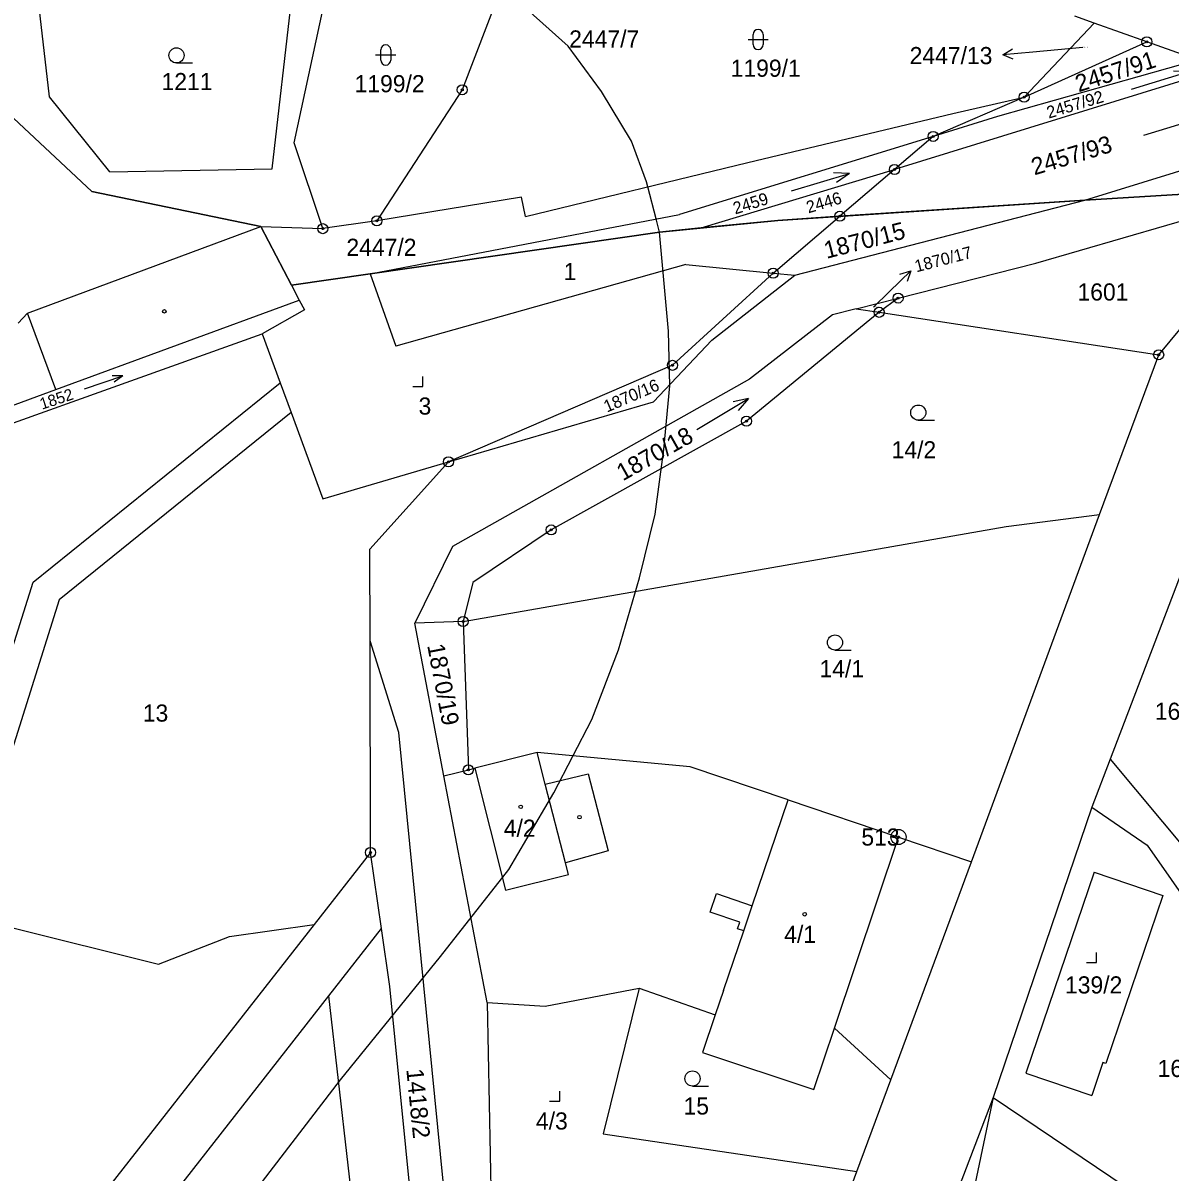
# Model space of a CAD drawing. Extents: x -546762 to -540209, y -1046851 to -1035694.
# Drawn here: x -543559.7 to -543445.9, y -1040689.9 to -1040575.9 of the extents above; entities that cross this region are included whole.
import ezdxf

# ---------------------------------------------------------------- set-up
doc = ezdxf.new("R2010")
doc.units = 0
for name, color, linetype in [('Vrstva 1', 7, 'Continuous'), ('Vrstva 13', 7, 'Continuous'), ('Vrstva 16', 7, 'Continuous'), ('Vrstva 17', 7, 'Continuous'), ('Vrstva 18', 7, 'Continuous'), ('Vrstva 19', 7, 'Continuous'), ('Vrstva 24', 7, 'Continuous'), ('Vrstva 25', 7, 'Continuous'), ('Vrstva 3', 7, 'Continuous'), ('Vrstva 30', 7, 'Continuous'), ('Vrstva 37', 7, 'Continuous'), ('Vrstva 4', 7, 'Continuous'), ('Vrstva 52', 7, 'Continuous')]:
    doc.layers.add(name, color=color, linetype=linetype)

msp = doc.modelspace()

# ---------------------------------------------------------------- linework, layer by layer
at = {"layer": 'Vrstva 1'}
for p, q in [((-543535.01, -1040590.37), (-543532.56, -1040569.26)), ((-543453.42, -1040575.92), (-543460.37, -1040583.26)), ((-543460.37, -1040583.26), (-543448.19, -1040577.78)), ((-543440.75, -1040580.42), (-543473.23, -1040590.44)), ((-543443.15, -1040579.57), (-543463, -1040585.19)), ((-543460.37, -1040583.26), (-543469.39, -1040587.16)), ((-543463, -1040585.19), (-543469.39, -1040587.16)), ((-543469.39, -1040587.16), (-543494.56, -1040594.9)), ((-543469.39, -1040587.16), (-543473.23, -1040590.44)), ((-543492.41, -1040596.24), (-543473.23, -1040590.44)), ((-543473.23, -1040590.44), (-543478.66, -1040595.08)), ((-543485.27, -1040600.73), (-543478.66, -1040595.08)), ((-543472.88, -1040603.2), (-543459.21, -1040599.73)), ((-543485.27, -1040600.73), (-543495.26, -1040609.87)), ((-543493.93, -1040599.87), (-543485.27, -1040600.73)), ((-543485.27, -1040600.73), (-543483.13, -1040600.94)), ((-543477.05, -1040604.26), (-543472.88, -1040603.2)), ((-543472.88, -1040603.2), (-543474.75, -1040604.61)), ((-543477.05, -1040604.26), (-543474.75, -1040604.61)), ((-543474.75, -1040604.61), (-543487.93, -1040615.41)), ((-543474.75, -1040604.61), (-543447.01, -1040608.82)), ((-543495.26, -1040609.87), (-543517.5, -1040619.45)), ((-543487.93, -1040615.41), (-543507.31, -1040626.2)), ((-543507.31, -1040626.2), (-543515.1, -1040631.43)), ((-543515.1, -1040631.43), (-543516.05, -1040635.29)), ((-543516.05, -1040635.29), (-543515.53, -1040650)), ((-543517.96, -1040650.61), (-543515.53, -1040650)), ((-543515.53, -1040650), (-543514.88, -1040649.84)), ((-543463.43, -1040682.52), (-543471.31, -1040703.06))]:
    msp.add_line(p, q, dxfattribs=at)
for points in [[(-543532.82, -1040587.78), (-543529.54, -1040572.59)], [(-543512.36, -1040572.67), (-543516.13, -1040582.53)], [(-543557.11, -1040583.24), (-543558.13, -1040574.33)], [(-543453.42, -1040575.92), (-543455.32, -1040575.24)], [(-543448.19, -1040577.78), (-543453.42, -1040575.92)], [(-543443.15, -1040579.57), (-543448.19, -1040577.78)], [(-543516.13, -1040582.53), (-543524.6, -1040595.53)], [(-543551.1, -1040590.66), (-543557.11, -1040583.24)], [(-543467.43, -1040584.9), (-543460.37, -1040583.26)], [(-543487.78, -1040589.76), (-543467.43, -1040584.9)], [(-543529.98, -1040596.31), (-543532.82, -1040587.78)], [(-543454.33, -1040593.48), (-543439.65, -1040588.95)], [(-543551.1, -1040590.66), (-543535.01, -1040590.37)], [(-543509.85, -1040595.1), (-543487.78, -1040589.76)], [(-543459.21, -1040599.73), (-543433.19, -1040592.18)], [(-543447.01, -1040608.82), (-543433.19, -1040592.18)], [(-543510.24, -1040593.2), (-543524.6, -1040595.53)], [(-543509.85, -1040595.1), (-543510.24, -1040593.2)], [(-543483.13, -1040600.94), (-543454.33, -1040593.48)], [(-543525.27, -1040600.79), (-543494.56, -1040594.9)], [(-543536.12, -1040596.1), (-543529.98, -1040596.31)], [(-543524.6, -1040595.53), (-543529.98, -1040596.31)], [(-543525.27, -1040600.79), (-543522.72, -1040607.98)], [(-543493.93, -1040599.87), (-543522.72, -1040607.98)], [(-543491.35, -1040607.37), (-543483.13, -1040600.94)], [(-543533.08, -1040601.92), (-543532.31, -1040603.39)], [(-543556.48, -1040612.28), (-543532.31, -1040603.39)], [(-543531.8, -1040604.36), (-543536, -1040606.75)], [(-543532.31, -1040603.39), (-543531.8, -1040604.36)], [(-543477.05, -1040604.26), (-543479.37, -1040604.85)], [(-543560.2, -1040605.68), (-543559.29, -1040604.69)], [(-543556.48, -1040612.28), (-543559.29, -1040604.69)], [(-543479.37, -1040604.85), (-543487.63, -1040611.24)], [(-543575.95, -1040621.03), (-543536, -1040606.75)], [(-543536, -1040606.75), (-543534.21, -1040611.62)], [(-543497.16, -1040613.5), (-543491.35, -1040607.37)], [(-543452.87, -1040624.67), (-543447.01, -1040608.82)], [(-543487.63, -1040611.24), (-543517.11, -1040627.83)], [(-543576.41, -1040619.61), (-543556.48, -1040612.28)], [(-543534.21, -1040611.62), (-543533.13, -1040614.55)], [(-543517.5, -1040619.45), (-543497.16, -1040613.5)], [(-543533.13, -1040614.55), (-543529.97, -1040623.1)], [(-543529.97, -1040623.1), (-543517.5, -1040619.45)], [(-543525.29, -1040628.11), (-543517.5, -1040619.45)], [(-543465.6, -1040659.12), (-543452.87, -1040624.67)], [(-543462.15, -1040625.86), (-543452.87, -1040624.67)], [(-543516.05, -1040635.29), (-543462.15, -1040625.86)], [(-543525.27, -1040637.19), (-543525.29, -1040628.11)], [(-543517.11, -1040627.83), (-543520.85, -1040635.46)], [(-543444.61, -1040630.05), (-543451.84, -1040648.94)], [(-543516.05, -1040635.29), (-543520.85, -1040635.46)], [(-543517.96, -1040650.61), (-543520.85, -1040635.46)], [(-543525.24, -1040658.21), (-543525.27, -1040637.19)], [(-543522.42, -1040646.29), (-543525.27, -1040637.19)], [(-543516.63, -1040704.88), (-543522.42, -1040646.29)], [(-543508.71, -1040648.29), (-543514.88, -1040649.84)], [(-543493.51, -1040649.69), (-543508.71, -1040648.29)], [(-543483.8, -1040652.97), (-543493.51, -1040649.69)], [(-543451.84, -1040648.94), (-543453.66, -1040653.7)], [(-543451.84, -1040648.94), (-543444.11, -1040658.18)], [(-543513.66, -1040673.1), (-543517.96, -1040650.61)], [(-543487.35, -1040663.48), (-543483.8, -1040652.97)], [(-543483.8, -1040652.97), (-543472.82, -1040656.68)], [(-543453.66, -1040653.7), (-543463.43, -1040682.52)], [(-543453.66, -1040653.7), (-543448.16, -1040657.49)], [(-543472.82, -1040656.68), (-543465.6, -1040659.12)], [(-543448.16, -1040657.49), (-543441, -1040667.68)], [(-543525.24, -1040658.21), (-543530.83, -1040665.34)], [(-543524.15, -1040665.74), (-543525.24, -1040658.21)], [(-543473.61, -1040680.77), (-543465.6, -1040659.12)], [(-543453.42, -1040660.16), (-543460.18, -1040680.1)], [(-543453.42, -1040660.16), (-543446.6, -1040662.48)], [(-543491.53, -1040664.13), (-543490.9, -1040662.28)], [(-543490.9, -1040662.28), (-543487.35, -1040663.48)], [(-543446.6, -1040662.48), (-543452.25, -1040679.14)], [(-543488.59, -1040665.12), (-543491.53, -1040664.13)], [(-543530.83, -1040665.34), (-543604.69, -1040759.58)], [(-543561.02, -1040665.62), (-543546.28, -1040669.29)], [(-543539.24, -1040666.55), (-543530.83, -1040665.34)], [(-543529.38, -1040672.42), (-543524.15, -1040665.74)], [(-543523.32, -1040671.49), (-543524.15, -1040665.74)], [(-543488.81, -1040665.78), (-543488.59, -1040665.12)], [(-543488.2, -1040665.99), (-543488.81, -1040665.78)], [(-543546.28, -1040669.29), (-543539.24, -1040666.55)], [(-543490.2, -1040671.91), (-543488.2, -1040665.99)], [(-543519.05, -1040714.41), (-543523.32, -1040671.49)], [(-543507.92, -1040673.46), (-543498.56, -1040671.65)], [(-543498.56, -1040671.65), (-543502.16, -1040686.11)], [(-543498.56, -1040671.65), (-543491.03, -1040674.32)], [(-543569.83, -1040724.11), (-543529.38, -1040672.42)], [(-543526.51, -1040697.64), (-543529.38, -1040672.42)], [(-543490.2, -1040671.91), (-543491.03, -1040674.32)], [(-543513.66, -1040673.1), (-543507.92, -1040673.46)], [(-543513.66, -1040673.1), (-543513.27, -1040693.2)], [(-543491.03, -1040674.32), (-543492.3, -1040678.04)], [(-543481.24, -1040681.72), (-543479.19, -1040675.62)], [(-543479.19, -1040675.62), (-543473.61, -1040680.77)], [(-543492.3, -1040678.04), (-543481.24, -1040681.72)], [(-543452.54, -1040679.05), (-543453.65, -1040682.31)], [(-543452.25, -1040679.14), (-543452.54, -1040679.05)], [(-543476.97, -1040689.86), (-543473.61, -1040680.77)], [(-543460.18, -1040680.1), (-543453.65, -1040682.31)], [(-543463.43, -1040682.52), (-543466.89, -1040698.87)], [(-543463.43, -1040682.52), (-543442.94, -1040696.32)], [(-543502.16, -1040686.11), (-543476.97, -1040689.86)], [(-543478.72, -1040694.6), (-543476.97, -1040689.86)]]:
    msp.add_lwpolyline(points, dxfattribs=at)
at = {"layer": 'Vrstva 13'}
for p, q in [((-543478.66, -1040595.08), (-543454.33, -1040593.48)), ((-543478.66, -1040595.08), (-543454.33, -1040593.48)), ((-543484.82, -1040595.49), (-543478.66, -1040595.08)), ((-543484.82, -1040595.49), (-543478.66, -1040595.08))]:
    msp.add_line(p, q, dxfattribs=at)
for points in [[(-543561.17, -1040584.9), (-543552.9, -1040592.63)], [(-543561.17, -1040584.9), (-543552.9, -1040592.63)], [(-543552.9, -1040592.63), (-543536.12, -1040596.1)], [(-543552.9, -1040592.63), (-543536.12, -1040596.1)], [(-543454.33, -1040593.48), (-543433.19, -1040592.18)], [(-543454.33, -1040593.48), (-543433.19, -1040592.18)], [(-543536.12, -1040596.1), (-543533.08, -1040601.92)], [(-543536.12, -1040596.1), (-543533.08, -1040601.92)], [(-543496.57, -1040596.65), (-543492.41, -1040596.24)], [(-543496.57, -1040596.65), (-543492.41, -1040596.24)], [(-543492.41, -1040596.24), (-543484.82, -1040595.49)], [(-543492.41, -1040596.24), (-543484.82, -1040595.49)], [(-543525.27, -1040600.79), (-543496.57, -1040596.65)], [(-543525.27, -1040600.79), (-543496.57, -1040596.65)], [(-543533.08, -1040601.92), (-543525.27, -1040600.79)], [(-543533.08, -1040601.92), (-543525.27, -1040600.79)]]:
    msp.add_lwpolyline(points, dxfattribs=at)
at = {"layer": 'Vrstva 16'}
for p, q in [((-543459.49, -1040578.8), (-543462.48, -1040579.07)), ((-543473.77, -1040602.58), (-543471.62, -1040600.49))]:
    msp.add_line(p, q, dxfattribs=at)
for points in [[(-543461.44, -1040579.48), (-543462.48, -1040579.07), (-543461.53, -1040578.48)], [(-543454.55, -1040578.35), (-543459.49, -1040578.8)], [(-543472.69, -1040600.83), (-543471.62, -1040600.49), (-543471.99, -1040601.54)], [(-543475.33, -1040604.1), (-543473.77, -1040602.58)]]:
    msp.add_lwpolyline(points, dxfattribs=at)
at = {"layer": 'Vrstva 24'}
for centre, radius in [((-543448.19, -1040577.78), 0.5), ((-543448.19, -1040577.78), 0.1), ((-543516.13, -1040582.53), 0.5), ((-543516.13, -1040582.53), 0.1), ((-543460.37, -1040583.26), 0.5), ((-543460.37, -1040583.26), 0.1), ((-543469.39, -1040587.16), 0.5), ((-543469.39, -1040587.16), 0.1), ((-543473.23, -1040590.44), 0.5), ((-543473.23, -1040590.44), 0.1), ((-543524.6, -1040595.53), 0.5), ((-543478.66, -1040595.08), 0.5), ((-543478.66, -1040595.08), 0.1), ((-543529.98, -1040596.31), 0.5), ((-543529.98, -1040596.31), 0.1), ((-543524.6, -1040595.53), 0.1), ((-543485.27, -1040600.73), 0.5), ((-543485.27, -1040600.73), 0.1), ((-543472.88, -1040603.2), 0.5), ((-543472.88, -1040603.2), 0.1), ((-543474.75, -1040604.61), 0.5), ((-543474.75, -1040604.61), 0.1), ((-543447.01, -1040608.82), 0.5), ((-543447.01, -1040608.82), 0.1), ((-543495.26, -1040609.87), 0.5), ((-543495.26, -1040609.87), 0.1), ((-543487.93, -1040615.41), 0.5), ((-543487.93, -1040615.41), 0.1), ((-543517.5, -1040619.45), 0.5), ((-543517.5, -1040619.45), 0.1), ((-543507.31, -1040626.2), 0.5), ((-543507.31, -1040626.2), 0.1), ((-543516.05, -1040635.29), 0.5), ((-543516.05, -1040635.29), 0.1), ((-543515.53, -1040650), 0.5), ((-543515.53, -1040650), 0.1), ((-543472.83, -1040656.67), 0.75), ((-543472.83, -1040656.67), 0.1), ((-543525.24, -1040658.21), 0.5), ((-543525.24, -1040658.21), 0.1)]:
    msp.add_circle(centre, radius, dxfattribs=at)
at = {"layer": 'Vrstva 25'}
for p, q in [((-543487.27, -1040578.04), (-543487.27, -1040577.04)), ((-543486.27, -1040577.04), (-543486.27, -1040578.04)), ((-543487.77, -1040577.54), (-543485.77, -1040577.54)), ((-543524.73, -1040579.08), (-543522.73, -1040579.08)), ((-543524.23, -1040579.58), (-543524.23, -1040578.58)), ((-543523.23, -1040578.58), (-543523.23, -1040579.58)), ((-543544.5, -1040579.87), (-543542.9, -1040579.87)), ((-543470.87, -1040615.31), (-543469.27, -1040615.31)), ((-543479.14, -1040638.12), (-543477.54, -1040638.12)), ((-543493.28, -1040681.38), (-543491.68, -1040681.38))]:
    msp.add_line(p, q, dxfattribs=at)
for points in [[(-543449.71, -1040582.47), (-543443.97, -1040580.73), (-543445.55, -1040580.69)], [(-543448.48, -1040587.02), (-543442.74, -1040585.28), (-543444.32, -1040585.24)], [(-543483.45, -1040592.55), (-543477.71, -1040590.83), (-543479.29, -1040590.78)], [(-543477.71, -1040590.83), (-543479, -1040591.74)], [(-543553.63, -1040612.19), (-543549.83, -1040610.91), (-543550.89, -1040610.91)], [(-543549.83, -1040610.91), (-543550.67, -1040611.55)], [(-543521.04, -1040611.97), (-543520.04, -1040611.97), (-543520.04, -1040610.97)], [(-543492.85, -1040616.24), (-543487.71, -1040613.16), (-543489.25, -1040613.5)], [(-543487.71, -1040613.16), (-543488.74, -1040614.36)], [(-543454.19, -1040669.13), (-543453.19, -1040669.13), (-543453.19, -1040668.13)], [(-543507.46, -1040682.88), (-543506.46, -1040682.88), (-543506.46, -1040681.88)]]:
    msp.add_lwpolyline(points, dxfattribs=at)
for centre, radius in [((-543544.5, -1040579.12), 0.75), ((-543545.7, -1040604.52), 0.175), ((-543470.87, -1040614.56), 0.75), ((-543479.14, -1040637.37), 0.75), ((-543510.33, -1040653.68), 0.175), ((-543504.5, -1040654.7), 0.175), ((-543482.14, -1040664.33), 0.175), ((-543493.28, -1040680.63), 0.75)]:
    msp.add_circle(centre, radius, dxfattribs=at)
for centre, start, end in [((-543486.77, -1040577.04), 0, 180), ((-543523.73, -1040578.58), 0, 180), ((-543486.77, -1040578.04), 180, 0), ((-543523.73, -1040579.58), 180, 0)]:
    msp.add_arc(centre, 0.5, start, end, dxfattribs=at)
at = {"layer": 'Vrstva 3'}
for points in [[(-543508.71, -1040648.29), (-543514.88, -1040649.84)], [(-543507.9, -1040651.42), (-543508.71, -1040648.29)], [(-543514.88, -1040649.84), (-543511.83, -1040661.93)], [(-543505.89, -1040659.22), (-543507.9, -1040651.42)], [(-543487.35, -1040663.48), (-543483.8, -1040652.97)], [(-543483.8, -1040652.97), (-543472.82, -1040656.68)], [(-543479.19, -1040675.62), (-543472.82, -1040656.68)], [(-543505.58, -1040660.4), (-543505.89, -1040659.22)], [(-543511.83, -1040661.93), (-543505.58, -1040660.4)], [(-543488.2, -1040665.99), (-543487.35, -1040663.48)], [(-543490.2, -1040671.91), (-543488.2, -1040665.99)], [(-543490.2, -1040671.91), (-543491.03, -1040674.32)], [(-543491.03, -1040674.32), (-543492.3, -1040678.04)], [(-543481.24, -1040681.72), (-543479.19, -1040675.62)], [(-543492.3, -1040678.04), (-543481.24, -1040681.72)]]:
    msp.add_lwpolyline(points, dxfattribs=at)
at = {"layer": 'Vrstva 30'}
for points in [[(-543558.73, -1040631.38), (-543534.21, -1040611.62)], [(-543534.21, -1040611.62), (-543533.13, -1040614.55)], [(-543533.13, -1040614.55), (-543556.14, -1040633.14)], [(-543568.97, -1040663.86), (-543558.73, -1040631.38)], [(-543556.14, -1040633.14), (-543566.03, -1040664.51)]]:
    msp.add_lwpolyline(points, dxfattribs=at)
at = {"layer": 'Vrstva 37'}
for centre in [(-543510.33, -1040653.68), (-543482.14, -1040664.33)]:
    msp.add_circle(centre, 0.175, dxfattribs=at)
at = {"layer": 'Vrstva 4'}
for points in [[(-543559.29, -1040604.69), (-543536.12, -1040596.1)], [(-543507.9, -1040651.42), (-543508.71, -1040648.29)], [(-543514.88, -1040649.84), (-543511.83, -1040661.93)], [(-543507.9, -1040651.42), (-543503.62, -1040650.39)], [(-543503.62, -1040650.39), (-543501.65, -1040658.05)], [(-543505.89, -1040659.22), (-543507.9, -1040651.42)], [(-543479.19, -1040675.62), (-543472.82, -1040656.68)], [(-543501.65, -1040658.05), (-543505.89, -1040659.22)], [(-543505.58, -1040660.4), (-543505.89, -1040659.22)], [(-543511.83, -1040661.93), (-543505.58, -1040660.4)], [(-543488.2, -1040665.99), (-543487.35, -1040663.48)]]:
    msp.add_lwpolyline(points, dxfattribs=at)
at = {"layer": 'Vrstva 52'}
for points in [[(-543496.57, -1040596.65), (-543525.27, -1040600.79), (-543533.08, -1040601.92), (-543536.12, -1040596.1), (-543552.9, -1040592.63), (-543561.17, -1040584.9), (-543563.03, -1040579.77), (-543571.38, -1040556.86)], [(-543496.57, -1040596.65), (-543496.9, -1040595.35), (-543497.71, -1040592.16), (-543497.84, -1040591.67), (-543499.33, -1040587.63), (-543502.32, -1040582.7), (-543505.61, -1040578.22), (-543511.58, -1040572.84), (-543511.85, -1040572.67), (-543512.26, -1040572.42), (-543513.49, -1040571.66), (-543517.41, -1040569.25), (-543523.53, -1040566.26)], [(-543563.03, -1040579.77), (-543561.17, -1040584.9), (-543552.9, -1040592.63), (-543536.12, -1040596.1), (-543533.08, -1040601.92), (-543525.27, -1040600.79), (-543496.57, -1040596.65)], [(-543496.57, -1040596.65), (-543484.82, -1040595.49), (-543454.33, -1040593.48), (-543433.19, -1040592.18), (-543425.03, -1040591.54), (-543423.93, -1040592.18)], [(-543413.87, -1040598.02), (-543423.93, -1040592.18), (-543425.03, -1040591.54), (-543433.19, -1040592.18), (-543454.33, -1040593.48), (-543478.66, -1040595.08), (-543484.82, -1040595.49), (-543492.41, -1040596.24), (-543496.57, -1040596.65)], [(-543761.66, -1041076.07), (-543723.84, -1040985.67), (-543700.74, -1040927.15), (-543689.29, -1040898.52), (-543681.03, -1040882.19), (-543673.88, -1040867.03), (-543658.41, -1040843.09), (-543543.36, -1040700.5), (-543528.22, -1040680.75), (-543518.29, -1040668.51), (-543511.51, -1040659.9), (-543507.03, -1040652.27), (-543503.28, -1040645), (-543500.61, -1040638.09), (-543498.55, -1040630.94), (-543496.98, -1040624.64), (-543496.13, -1040618.22), (-543495.53, -1040611.92), (-543495.65, -1040606.47), (-543496.57, -1040596.65)]]:
    msp.add_lwpolyline(points, dxfattribs=at)

# ---------------------------------------------------------------- texts
at = {"layer": 'Vrstva 16'}
for s, p in [('2447/7', (-543505.52, -1040578.34)), ('2447/13', (-543471.73, -1040579.99))]:
    msp.add_text(s, height=1.7, dxfattribs=at).set_placement(p)
msp.add_text('1870/17', height=1.2, rotation=14.522, dxfattribs=at).set_placement((-543471.06, -1040600.65))
at = {"layer": 'Vrstva 17'}
msp.add_text('513', height=1.7, dxfattribs=at).set_placement((-543476.52, -1040657.52))
at = {"layer": 'Vrstva 18'}
for s, height, rotation, p in [('2457/91', 1.7, 18, (-543454.96, -1040582.79)), ('2457/92', 1.2, 16.8241, (-543457.92, -1040585.4)), ('2457/93', 1.7, 16.8241, (-543459.35, -1040591.03)), ('2459', 1.2, 17.5424, (-543489.04, -1040594.91)), ('2446', 1.2, 16.8241, (-543481.78, -1040594.8)), ('1870/15', 1.7, 14.522, (-543479.98, -1040599.31)), ('1870/16', 1.2, 23.314, (-543501.78, -1040614.57)), ('1852', 1.14, 18.285, (-543557.85, -1040614.28)), ('1870/18', 1.7, 29.3688, (-543500.2, -1040621.39)), ('1870/19', 1.7, 280.7999, (-543519.62, -1040637.65)), ('1418/2', 1.7, 275.6815, (-543521.69, -1040679.73))]:
    msp.add_text(s, height=height, rotation=rotation, dxfattribs=at).set_placement(p)
for s, height, p in [('2447/13', 0.1, (-543454.55, -1040578.35)), ('1199/1', 1.7, (-543489.49, -1040581.24)), ('1211', 1.7, (-543545.98, -1040582.57)), ('1199/2', 1.7, (-543526.82, -1040582.78)), ('2447/2', 1.7, (-543527.63, -1040599.01)), ('1', 1.7, (-543506.07, -1040601.41)), ('1601', 1.7, (-543455.07, -1040603.44)), ('1870/17', 0.1, (-543475.33, -1040604.1)), ('14/2', 1.7, (-543473.52, -1040619.1)), ('14/1', 1.7, (-543480.68, -1040640.82)), ('13', 1.7, (-543547.84, -1040645.22)), ('1603/3', 1.7, (-543447.39, -1040645.04)), ('1605/1', 1.7, (-543447.12, -1040680.48)), ('15', 1.7, (-543494.17, -1040684.2))]:
    msp.add_text(s, height=height, dxfattribs=at).set_placement(p)
at = {"layer": 'Vrstva 19'}
for s, p in [('3', (-543520.47, -1040614.76)), ('4/2', (-543512.01, -1040656.64)), ('4/1', (-543484.18, -1040667.17)), ('139/2', (-543456.31, -1040672.19)), ('4/3', (-543508.82, -1040685.69))]:
    msp.add_text(s, height=1.7, dxfattribs=at).set_placement(p)

doc.saveas('drawing.dxf')
